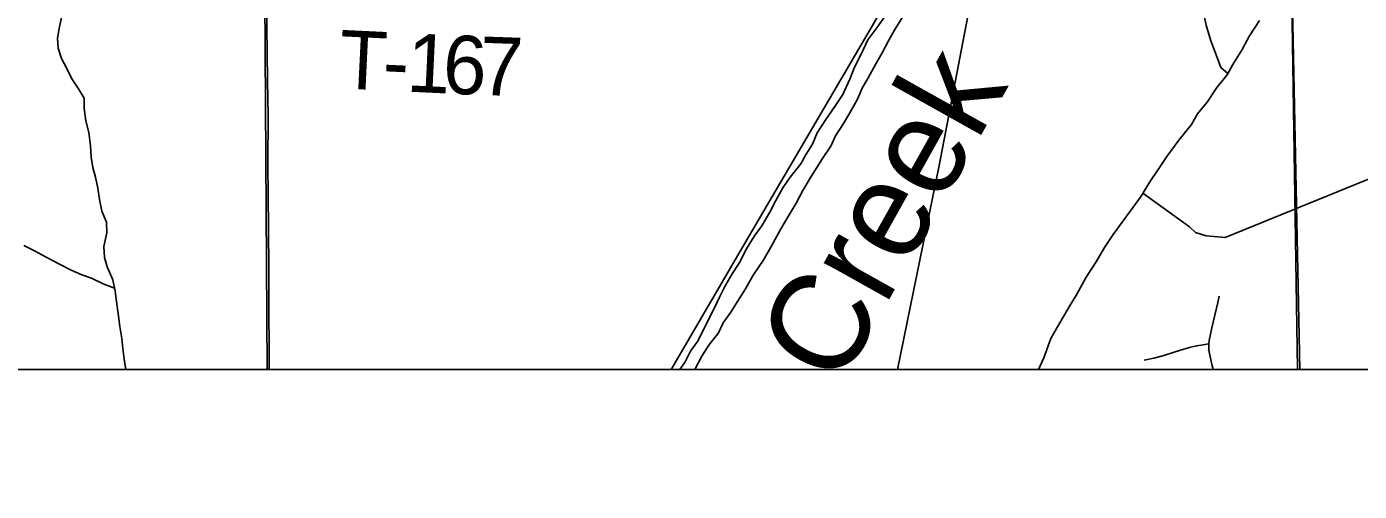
# Model space of a CAD drawing. Extents: x 0 to 34, y 0 to 22.
# Drawn here: x 6.57 to 7.864, y 16.861 to 17.313 of the extents above; entities that cross this region are included whole.
import ezdxf

# ---------------------------------------------------------------- set-up
doc = ezdxf.new("R2010")
doc.units = 0
for name, color, linetype in [('GM_X_Major_River', 7, 'Continuous'), ('GM_X_Major_River_Text', 7, 'Continuous'), ('GM_X_Minor_River', 7, 'Continuous'), ('GM_X_Rail_Line', 7, 'Continuous'), ('GM_X_Section', 7, 'Continuous'), ('GM_X_State_Route', 7, 'Continuous'), ('GM_X_Township_Road', 7, 'Continuous'), ('GM_X_Township_Road_Text', 7, 'Continuous'), ('SH_Text', 7, 'Continuous')]:
    doc.layers.add(name, color=color, linetype=linetype)

msp = doc.modelspace()

# ---------------------------------------------------------------- linework, layer by layer
at = {"layer": 'GM_X_Major_River'}
for points in [[(7.4033, 17.3224), (7.3954, 17.3114), (7.3868, 17.2996), (7.3804, 17.2866), (7.3737, 17.2733), (7.3692, 17.2615), (7.3624, 17.2467), (7.3545, 17.2349), (7.3459, 17.2223), (7.3376, 17.2094), (7.3328, 17.1984), (7.3268, 17.1888), (7.3215, 17.1793), (7.3114, 17.1664), (7.3042, 17.1561), (7.2975, 17.1439), (7.2915, 17.1325), (7.2836, 17.1192), (7.2768, 17.1093), (7.269, 17.0967), (7.2618, 17.083), (7.2551, 17.0724), (7.2479, 17.0602), (7.2427, 17.0499), (7.2375, 17.0389), (7.2322, 17.029), (7.2266, 17.0168), (7.2213, 17.0069), (7.2146, 16.9974), (7.2093, 16.9871), (7.2042, 16.9797)], [(7.2188, 16.9797), (7.2256, 16.9925), (7.2323, 17.0032), (7.2417, 17.0154), (7.2462, 17.0249), (7.2537, 17.0355), (7.2601, 17.0458), (7.268, 17.058), (7.2755, 17.0713), (7.2849, 17.0854), (7.2924, 17.0983), (7.3018, 17.1155), (7.3104, 17.1299), (7.3172, 17.141), (7.3235, 17.1535), (7.3318, 17.1669), (7.3427, 17.1844), (7.3506, 17.1965), (7.3554, 17.2064), (7.3629, 17.2186), (7.3693, 17.2289), (7.3765, 17.2422), (7.3813, 17.2529), (7.387, 17.2628), (7.3941, 17.2757), (7.4005, 17.2871), (7.4068, 17.2989), (7.4128, 17.3099), (7.4203, 17.3217)]]:
    msp.add_lwpolyline(points, dxfattribs=at)
at = {"layer": 'GM_X_Minor_River'}
for points in [[(7.6537, 17.1508), (7.699, 17.1181), (7.7047, 17.1128), (7.7153, 17.1095), (7.7335, 17.1077), (8.108, 17.2601), (8.1144, 17.2635), (8.1269, 17.2742), (8.1476, 17.365)], [(7.7362, 17.2671), (7.7293, 17.2727), (7.725, 17.2852), (7.7197, 17.2989), (7.7151, 17.314), (7.7127, 17.3258), (7.7127, 17.3391), (7.7164, 17.3486), (7.7232, 17.3623), (7.736, 17.3714), (7.7488, 17.3723)], [(6.6662, 16.9797), (6.6646, 16.9898), (6.6635, 17), (6.6624, 17.0099), (6.6606, 17.0213), (6.6588, 17.0342), (6.6573, 17.0456), (6.6558, 17.0558), (6.6536, 17.0668), (6.6483, 17.0794), (6.6457, 17.0885), (6.645, 17.0991), (6.6477, 17.1124), (6.6474, 17.1227), (6.6429, 17.1333), (6.6406, 17.1447), (6.6392, 17.1557), (6.6369, 17.1663), (6.6343, 17.1758), (6.6325, 17.1857), (6.6321, 17.1967), (6.6303, 17.2096), (6.6273, 17.221), (6.6259, 17.2332), (6.6259, 17.243), (6.6203, 17.2522), (6.6139, 17.2617), (6.609, 17.272), (6.6037, 17.2815), (6.6007, 17.2917), (6.6, 17.3012), (6.6016, 17.3107), (6.6039, 17.3213)], [(7.5525, 16.9797), (7.5577, 16.9911), (7.5644, 17.0097), (7.5708, 17.0211), (7.5821, 17.0405), (7.5892, 17.0523), (7.5986, 17.0694), (7.6084, 17.0843), (7.6166, 17.098), (7.6249, 17.1109), (7.6373, 17.1277), (7.6444, 17.1372), (7.6519, 17.1479), (7.6606, 17.162), (7.6685, 17.1738), (7.6771, 17.1863), (7.6887, 17.2023), (7.7008, 17.2176), (7.7068, 17.2278), (7.7162, 17.2393), (7.7256, 17.2534), (7.7354, 17.2656), (7.741, 17.2758), (7.75, 17.2903), (7.7571, 17.3036), (7.7669, 17.3185)], [(6.6553, 17.0585), (6.6441, 17.0627), (6.6328, 17.0685), (6.6234, 17.0715), (6.6132, 17.0762), (6.6018, 17.0819), (6.589, 17.0888), (6.5777, 17.0949), (6.5671, 17.0999)]]:
    msp.add_lwpolyline(points, dxfattribs=at)
at = {"layer": 'GM_X_Rail_Line'}
for points in [[(7.4155, 16.9797), (7.4558, 17.1778), (7.5178, 17.4999), (7.5426, 17.6225), (7.5717, 17.7043), (7.6321, 17.8584), (7.8825, 18.4937), (8.0236, 18.8584), (8.1515, 19.1722), (8.1675, 19.2314), (8.3282, 19.8945)], [(7.1956, 16.9797), (7.2748, 17.1151), (7.3911, 17.3137), (7.4282, 17.3794), (7.4457, 17.4145), (7.4643, 17.4578), (7.6315, 17.8854), (7.7259, 18.128), (7.7853, 18.2725), (7.8783, 18.5108), (8.1687, 19.2471)]]:
    msp.add_lwpolyline(points, dxfattribs=at)
at = {"layer": 'GM_X_Section'}
for points in [[(7.9972, 16.8792), (8.802, 16.8756), (8.8106, 17.3801), (8.8027, 17.8763), (7.7942, 17.8673), (7.7942, 17.5709), (7.8062, 16.9797), (7.9972, 16.9797)], [(7.8062, 16.9797), (7.7942, 17.5709), (7.7942, 17.8673), (6.7979, 17.8558), (6.8036, 16.9797)], [(6.8036, 16.9797), (6.7979, 17.8558), (5.6465, 17.841), (5.6459, 16.8927), (5.644, 16.8278), (5.7774, 16.8294), (5.7774, 16.9797)]]:
    msp.add_lwpolyline(points, close=True, dxfattribs=at)
at = {"layer": 'GM_X_State_Route'}
msp.add_lwpolyline([(5.7774, 16.9797), (7.8038, 16.9797), (7.7904, 17.865), (8.296, 17.8766), (8.8033, 17.8763), (8.7984, 18.8872), (8.9, 18.8876), (8.9, 20.9), (5.6507, 20.9)], dxfattribs=at)
msp.add_lwpolyline([(7.8042, 16.2626), (7.8024, 15.8725), (6.7968, 15.8774), (5.6416, 15.8841), (5.6436, 15.468), (5.6455, 14.1), (8.9, 14.1), (8.9, 18.8876), (8.7984, 18.8872), (8.8033, 17.8763), (8.296, 17.8766), (7.7904, 17.865), (7.8038, 16.9797), (7.9972, 16.9797), (7.9972, 16.2626)], close=True, dxfattribs=at)
at = {"layer": 'GM_X_Township_Road'}
for points in [[(6.8055, 16.9797), (6.8053, 16.9961), (6.8052, 17.0396), (6.8051, 17.0769), (6.8048, 17.1173), (6.8042, 17.1794), (6.8043, 17.226), (6.8037, 17.2602), (6.8033, 17.313), (6.8029, 17.3409), (6.8028, 17.3532)], [(7.7219, 16.9797), (7.7209, 16.9833), (7.7183, 16.9951), (7.7178, 16.9983), (7.7176, 17.0014), (7.7178, 17.0045), (7.7181, 17.0077), (7.7208, 17.02), (7.7266, 17.0446), (7.7279, 17.0508)], [(7.6551, 16.9888), (7.6642, 16.9908), (7.6732, 16.993), (7.6851, 16.9967), (7.7, 17.0013), (7.706, 17.0028), (7.7122, 17.0037), (7.7178, 17.0045)]]:
    msp.add_lwpolyline(points, dxfattribs=at)
at = {"layer": 'SH_Text'}
msp.add_lwpolyline([(5.7774, 16.9797), (7.9972, 16.9797), (7.9972, 16.2626), (5.7774, 16.2626)], close=True, dxfattribs=at)

# ---------------------------------------------------------------- texts
at = {"layer": 'GM_X_Major_River_Text'}
msp.add_text('Creek', height=0.09472, rotation=60.7664, dxfattribs=at).set_placement((7.3585, 16.9603))
at = {"layer": 'GM_X_Township_Road_Text'}
for s, rotation, p in [('T', 357.2497, (6.8723, 17.2527)), ('1', 357.2944, (6.9381, 17.2495)), ('6', 357.4243, (6.9732, 17.2479)), ('7', 357.9692, (7.0088, 17.2463)), ('-', 357.2565, (6.9148, 17.2506))]:
    msp.add_text(s, height=0.0568, rotation=rotation, dxfattribs=at).set_placement(p)

doc.saveas('drawing.dxf')
